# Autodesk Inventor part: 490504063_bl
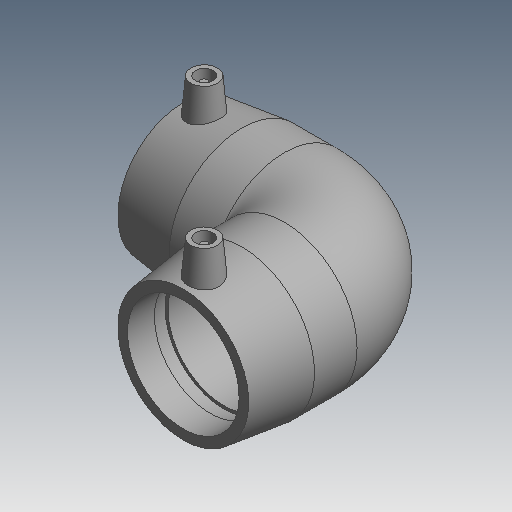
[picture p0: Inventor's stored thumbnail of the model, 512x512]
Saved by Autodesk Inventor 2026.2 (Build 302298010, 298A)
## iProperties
Created: 2017-06
Part Number: 490504063_bl
Material: Generic
Description: PLASSON 90° ELBOW 63
Document SubType Name: Modeling
Designer: KIM
Mass: 55.0731 g
Surface Area: 148.067 cm^2
Volume: 55.0731 cm^3
Density: 1 g/cm^3
Appearance: Default
Author: KIM
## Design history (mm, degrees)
derived "490504 -20-75.ipt"
feature "Solid1::490504 -20-75.ipt" dims "ScaleForDerivedMember" = 10
tag "TaggingFeature1"
body "Solid1"
other parameters: "d2" = 82 [user parameter], "d4" = 33 [user parameter], "d5" = 73.8 [user parameter], "d8" = 168 deg [user parameter], "d10" = 22.8 [user parameter], "d11" = 7.6 [user parameter], "d14" = 17.6296 [user parameter], "d18" = 63 [user parameter], "d19" = 3.52592 [user parameter], "d20" = 168 deg [user parameter], "d22" = 75.44 [user parameter], "d23" = 82 [user parameter], "d24" = 73.1768 [user parameter], "d29" = 56 [user parameter], "d30" = 15 [user parameter], "d31" = 79.2 [user parameter], "d34" = 5 deg [user parameter], "d35" = 15 [user parameter], "d39" = 5 deg [user parameter], "d41" = 4 [user parameter], "d42" = 14 [user parameter], "d43" = 0 [user parameter], "d45" = 4 [user parameter], "d46" = 14 [user parameter], "d47" = 0 [user parameter], "d49" = 63 [user parameter], "d50" = 53.55 [user parameter], "d51" = 22.8 [user parameter], "d52" = 57 [user parameter], "d54" = 90 deg [user parameter], "d65" = 63 [user parameter], "d67" = 45 deg [user parameter], "d71" = 90 deg [user parameter], "d75" = 4.1 [user parameter], "d82" = 45 deg [user parameter], "d83" = 57 [user parameter], "d84" = 73.8 [user parameter], "d87" = 90 deg [user parameter], "d90" = 57 [user parameter], "d91" = 0 [user parameter], "d92" = 57 [user parameter], "d93" = 0 [user parameter], "d94" = 90 deg [user parameter], "d101" = 3 [user parameter], "d102" = 0 [user parameter], "d103" = 3 [user parameter], "d104" = 0 [user parameter], "d105" = 16.53 [user parameter], "d106" = 4.1325 [user parameter], "d110" = 31.35 [user parameter], "d111" = 132 [user parameter], "d112" = 132 [user parameter], "d113" = 132 [user parameter], "d114" = 132 [user parameter], "d_" = 63 [user parameter], "L_" = 132 [user parameter], "L_1" = 57 [user parameter], "D_" = 82 [user parameter], "A_" = 56 [user parameter], "d_2" = 12 [user parameter]
